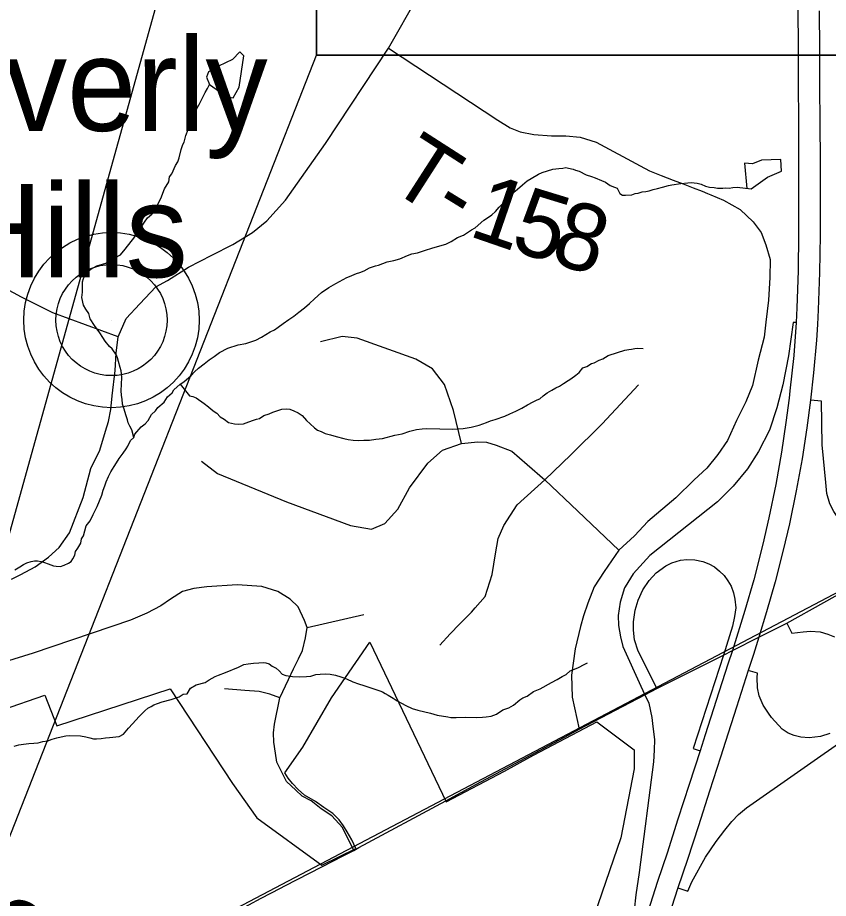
# Model space of a CAD drawing. Extents: x 44.2 to 78.2, y 4.5 to 26.5.
# Drawn here: x 50.361 to 51.048, y 22.487 to 23.234 of the extents above; entities that cross this region are included whole.
import ezdxf

# ---------------------------------------------------------------- set-up
doc = ezdxf.new("R2010")
doc.units = 0
for name, color, linetype in [('GM_X_Corporation', 7, 'Continuous'), ('GM_X_County_Road', 7, 'Continuous'), ('GM_X_Interchange_Ramps', 7, 'Continuous'), ('GM_X_Interstate_Route', 7, 'Continuous'), ('GM_X_Minor_Lake', 7, 'Continuous'), ('GM_X_Minor_River', 7, 'Continuous'), ('GM_X_Rail_Line', 7, 'Continuous'), ('GM_X_State_Route', 7, 'Continuous'), ('GM_X_Township_Road', 7, 'Continuous'), ('GM_X_Township_Road_Text', 7, 'Continuous'), ('GM_X_Unincorporated', 7, 'Continuous'), ('GM_X_Unincorporated_Location', 7, 'Continuous'), ('GM_X_Unincorporated_Text', 7, 'Continuous'), ('SH_Data', 7, 'Continuous')]:
    doc.layers.add(name, color=color, linetype=linetype)

msp = doc.modelspace()

# ---------------------------------------------------------------- linework, layer by layer
at = {"layer": 'GM_X_Corporation'}
msp.add_lwpolyline([(50.31156, 22.63401), (50.38364, 22.65883), (50.39385, 22.63306), (50.49002, 22.66436), (50.54291, 22.58409), (50.56344, 22.55477), (50.61853, 22.51475), (50.64753, 22.52885), (50.64407, 22.53609), (50.64003, 22.54311), (50.6369, 22.54819), (50.63346, 22.55312), (50.62793, 22.55864), (50.62046, 22.56357), (50.61315, 22.56865), (50.60403, 22.57403), (50.59851, 22.57881), (50.59387, 22.58404), (50.59014, 22.58852), (50.58715, 22.593), (50.60239, 22.61481), (50.62675, 22.65684), (50.65945, 22.70384), (50.72413, 22.56852), (50.77347, 22.59448), (50.79516, 22.60637), (50.79886, 22.60841), (50.8519, 22.63647), (50.88361, 22.61259), (50.88361, 22.59645), (50.87224, 22.5379), (50.84648, 22.46307)], dxfattribs=at)
at = {"layer": 'GM_X_County_Road'}
for points in [[(50.67528, 23.20811), (50.70031, 23.25252), (50.70921, 23.26368), (50.72749, 23.2982), (50.73832, 23.32832), (50.74576, 23.34795), (50.75659, 23.37604), (50.77337, 23.43186), (50.8174, 23.53966), (50.84536, 23.61043), (50.86798, 23.67979), (50.87273, 23.69294), (50.87551, 23.70196), (50.87354, 23.71004), (50.86808, 23.71791), (50.86065, 23.72293), (50.8576, 23.7273), (50.85497, 23.73517), (50.85476, 23.74587), (50.85912, 23.77099), (50.86196, 23.78672)], [(50.35523, 22.75754), (50.36339, 22.7613), (50.37531, 22.76789), (50.38661, 22.77605), (50.39571, 22.78421), (50.40449, 22.79676), (50.4161, 22.82657), (50.42262, 22.85131), (50.43022, 22.86673), (50.43524, 22.88304), (50.43775, 22.8912), (50.43964, 22.90124), (50.44089, 22.91285), (50.4434, 22.9345), (50.44403, 22.94925), (50.44591, 22.96306), (50.4525, 22.97874), (50.46429, 22.99111), (50.47791, 23.00539), (50.48764, 23.01075), (50.50553, 23.02204), (50.52529, 23.0324), (50.54318, 23.0415), (50.55981, 23.05154), (50.57205, 23.06158), (50.58773, 23.07915), (50.62162, 23.12716), (50.67528, 23.20811)]]:
    msp.add_lwpolyline(points, dxfattribs=at)
at = {"layer": 'GM_X_Interchange_Ramps'}
for points in [[(51.02104, 22.97511), (51.01857, 22.97527), (51.01465, 22.94684), (51.00975, 22.92233), (51.00452, 22.90272), (50.99831, 22.88377), (50.98916, 22.86579), (50.97969, 22.85109), (50.9676, 22.83638), (50.9542, 22.82298), (50.89701, 22.77756), (50.88288, 22.76188), (50.87595, 22.75088)], [(51.12221, 22.78472), (51.11418, 22.79428), (51.10871, 22.79237), (51.10379, 22.79125), (51.09767, 22.79057), (51.09122, 22.79069), (51.0851, 22.79159), (51.07777, 22.79375), (51.07059, 22.79718), (51.0643, 22.80152), (51.05786, 22.8078), (51.05289, 22.81477), (51.04962, 22.82141), (51.04704, 22.83), (51.04606, 22.8394), (51.04319, 22.87135), (51.04263, 22.90847), (51.03314, 22.90939)], [(50.90282, 22.6647), (50.8992, 22.67224), (50.88693, 22.69639), (50.88399, 22.706), (50.88292, 22.71401), (50.88292, 22.72108), (50.88439, 22.73122), (50.88693, 22.73949), (50.89093, 22.74843), (50.89627, 22.75617), (50.9024, 22.76284), (50.91041, 22.76884), (50.91561, 22.77138), (50.92295, 22.77351), (50.92842, 22.77418), (50.93509, 22.77378), (50.94176, 22.77245), (50.94697, 22.77031), (50.95164, 22.76791), (50.95604, 22.76431), (50.95991, 22.76057), (50.96311, 22.75604), (50.96592, 22.75137), (50.96792, 22.74576), (50.96912, 22.74056), (50.96978, 22.73295), (50.96872, 22.72562), (50.96698, 22.71748), (50.95933, 22.69286), (50.93376, 22.61367), (50.9395, 22.61186)], [(50.87595, 22.75088), (50.87542, 22.75004), (50.87169, 22.73798), (50.87016, 22.72657), (50.87038, 22.71802), (50.87191, 22.70837), (50.87411, 22.70025), (50.88912, 22.66664), (50.89262, 22.65931)], [(51.0131, 22.72011), (51.01724, 22.71163), (51.02699, 22.71267), (51.03333, 22.71326), (51.0413, 22.71267), (51.0478, 22.71075), (51.05355, 22.70854)], [(51.0496, 22.62647), (51.04168, 22.62382), (51.03213, 22.62277), (51.02492, 22.62342), (51.01936, 22.62481), (51.01426, 22.62682), (51.0092, 22.63018), (51.00015, 22.64009), (50.99758, 22.64358), (50.99299, 22.65036), (50.98962, 22.65833), (50.9881, 22.66526), (50.98784, 22.67404), (50.98826, 22.67755), (50.98029, 22.67996)], [(50.89262, 22.65931), (50.89602, 22.65216), (50.89857, 22.64), (50.89938, 22.63243), (50.90075, 22.62129), (50.90064, 22.6123), (50.89988, 22.60243), (50.88781, 22.50834), (50.88507, 22.48959), (50.88346, 22.47638), (50.87865, 22.45129), (50.85224, 22.3603), (50.85784, 22.35887)], [(50.92077, 22.49533), (50.9292, 22.49272), (50.93261, 22.50056), (50.94399, 22.52157), (50.95314, 22.5348), (50.96041, 22.54433), (50.96638, 22.55182), (50.97219, 22.55769), (50.97891, 22.56323), (51.06835, 22.62599), (51.07701, 22.63433), (51.08499, 22.64322), (51.08921, 22.64897), (51.09083, 22.65184)]]:
    msp.add_lwpolyline(points, dxfattribs=at)
at = {"layer": 'GM_X_Interstate_Route'}
for points in [[(51.02245, 23.24126), (51.02259, 23.20888), (51.02273, 23.1777), (51.02291, 23.1461), (51.02291, 23.11441), (51.02296, 23.08351), (51.02291, 23.05053), (51.02259, 23.01916), (51.02149, 22.98761), (51.02104, 22.97511), (51.01892, 22.94725), (51.01575, 22.9173), (51.01497, 22.91101), (51.0123, 22.89044), (51.00845, 22.86509), (51.00372, 22.83762), (50.99798, 22.80952), (50.99279, 22.78724), (50.98498, 22.75684), (50.97754, 22.73085), (50.96707, 22.69682), (50.96293, 22.6852), (50.95315, 22.65434), (50.94374, 22.62518), (50.9395, 22.61186), (50.93024, 22.58302), (50.92078, 22.55367), (50.9115, 22.52501), (50.90351, 22.50081), (50.89515, 22.47509)], [(51.04062, 23.23964), (51.04076, 23.20726), (51.0409, 23.17608), (51.04108, 23.14448), (51.04137, 23.11247), (51.04147, 23.08195), (51.04132, 23.04925), (51.04076, 23.01755), (51.03966, 22.98599), (51.03921, 22.97349), (51.03829, 22.96014), (51.03585, 22.93245), (51.03314, 22.90939), (51.03014, 22.88573), (51.02606, 22.85964), (51.02107, 22.83238), (51.01533, 22.80428), (51.01014, 22.782), (51.0031, 22.75502), (50.99594, 22.72977), (50.9894, 22.70822), (50.98481, 22.69344), (50.98029, 22.67996), (50.97042, 22.64885), (50.961, 22.61969), (50.95677, 22.60638), (50.9475, 22.57753), (50.93804, 22.54819), (50.92876, 22.51953), (50.92077, 22.49533), (50.9128, 22.47081)]]:
    msp.add_lwpolyline(points, dxfattribs=at)
at = {"layer": 'GM_X_Minor_Lake'}
for points in [[(50.52321, 23.1771), (50.53839, 23.16684), (50.54331, 23.16598), (50.54843, 23.17499), (50.55239, 23.2015), (50.54905, 23.20499), (50.54283, 23.19828), (50.53094, 23.19283), (50.52248, 23.18806)], [(50.97109, 23.08991), (50.98283, 23.08852), (50.99671, 23.09849), (51.00859, 23.10356), (51.00804, 23.11345), (50.99169, 23.11303)]]:
    msp.add_lwpolyline(points, dxfattribs=at)
at = {"layer": 'GM_X_Minor_River'}
for points in [[(50.52248, 23.18806), (50.52075, 23.18334), (50.52321, 23.1771)], [(50.45907, 22.87769), (50.45733, 22.88418), (50.45589, 22.88725), (50.45444, 22.88995), (50.45375, 22.89262), (50.45234, 22.89683), (50.45094, 22.90179), (50.44953, 22.906), (50.44925, 22.91018), (50.44857, 22.91323), (50.4483, 22.91741), (50.44881, 22.9227), (50.44896, 22.92877), (50.44834, 22.93409), (50.44765, 22.93714), (50.44626, 22.94211), (50.4452, 22.94517), (50.4445, 22.94746), (50.44083, 22.95287), (50.4386, 22.95482), (50.43492, 22.95947), (50.43272, 22.96256), (50.43016, 22.96642), (50.42576, 22.9726), (50.42211, 22.97839), (50.42108, 22.98296), (50.41851, 22.98644), (50.41632, 22.98992), (50.41496, 22.9964), (50.41546, 23.00093), (50.41568, 23.00965), (50.41651, 23.01266), (50.41892, 23.01753), (50.42279, 23.02046), (50.4278, 23.02336), (50.43545, 23.02544), (50.44045, 23.02796), (50.44509, 23.03125), (50.44778, 23.0327), (50.4517, 23.03753), (50.45994, 23.04793), (50.4612, 23.05282), (50.46508, 23.05576), (50.4706, 23.06395), (50.47448, 23.06726), (50.47684, 23.07024), (50.47924, 23.0751), (50.48203, 23.08034), (50.48527, 23.0886), (50.48885, 23.09457), (50.48933, 23.09873), (50.49129, 23.10133), (50.49451, 23.10845), (50.49649, 23.11144), (50.49771, 23.11482), (50.49941, 23.12198), (50.50066, 23.12612), (50.50185, 23.12836), (50.50313, 23.13401), (50.50516, 23.13889), (50.50597, 23.14114), (50.50838, 23.14639), (50.50922, 23.1494), (50.51284, 23.15727), (50.51441, 23.1595), (50.51682, 23.16475), (50.51802, 23.167), (50.51962, 23.17036), (50.52161, 23.17373), (50.52321, 23.1771)], [(50.99169, 23.11303), (50.98402, 23.10977), (50.9772, 23.11029), (50.97916, 23.08896)], [(50.44447, 22.85608), (50.44684, 22.85981), (50.45, 22.86428), (50.45275, 22.868), (50.45394, 22.87024), (50.45635, 22.87511), (50.45907, 22.87769), (50.45989, 22.88032), (50.46537, 22.88663), (50.46885, 22.88919), (50.47121, 22.89216), (50.47399, 22.89702), (50.47749, 22.90034), (50.47946, 22.90294), (50.48489, 22.90773), (50.48767, 22.91221), (50.49155, 22.91552), (50.49313, 22.91813), (50.49857, 22.92292), (50.50165, 22.92473), (50.50787, 22.93026), (50.5106, 22.93322), (50.51411, 22.93654), (50.51876, 22.94021), (50.52302, 22.94351), (50.52727, 22.94644), (50.53191, 22.94973), (50.53884, 22.95334), (50.54765, 22.95614), (50.55413, 22.95749), (50.56256, 22.9603), (50.56756, 22.96282), (50.57489, 22.96718), (50.57835, 22.96899), (50.58145, 22.97118), (50.58571, 22.97448), (50.59073, 22.97776), (50.59498, 22.98069), (50.59924, 22.98399), (50.60389, 22.98766), (50.60816, 22.99134), (50.61244, 22.9954), (50.61827, 23.00055), (50.62446, 23.00494), (50.63062, 23.00819), (50.63986, 23.01326), (50.64217, 23.01434), (50.64793, 23.01684), (50.65098, 23.01752), (50.65444, 23.01895), (50.65906, 23.02148), (50.66404, 23.02325), (50.66672, 23.02393), (50.674, 23.02678), (50.67973, 23.02776), (50.6847, 23.02915), (50.69123, 23.03201), (50.69506, 23.03343), (50.69965, 23.03445), (50.70653, 23.03654), (50.7119, 23.0383), (50.71687, 23.03968), (50.72376, 23.04178), (50.72837, 23.04393), (50.73377, 23.0472), (50.73876, 23.04935), (50.74571, 23.05372), (50.74879, 23.05553), (50.75618, 23.06216), (50.75926, 23.06398), (50.76274, 23.06654), (50.76586, 23.0695), (50.76899, 23.0732), (50.77249, 23.07653), (50.776, 23.08023), (50.7799, 23.08429), (50.78456, 23.08834), (50.78883, 23.09202), (50.79272, 23.09533), (50.79619, 23.09752), (50.80236, 23.10115), (50.80543, 23.10259), (50.81462, 23.10538), (50.81957, 23.10601), (50.823, 23.1063), (50.82566, 23.10661), (50.82793, 23.10617), (50.83171, 23.10531), (50.83397, 23.10449), (50.83698, 23.10366), (50.84298, 23.10046), (50.84751, 23.09921), (50.85051, 23.09799), (50.85577, 23.09558), (50.85916, 23.09435), (50.86327, 23.09159), (50.86702, 23.08998), (50.86928, 23.08916), (50.87036, 23.08685), (50.87144, 23.08455), (50.87369, 23.08335)], [(50.87369, 23.08335), (50.87635, 23.08329), (50.88167, 23.08353), (50.88436, 23.08459), (50.88703, 23.0849), (50.89047, 23.08595), (50.89352, 23.08625), (50.89619, 23.08694), (50.89964, 23.08798), (50.90346, 23.08902), (50.90767, 23.09005), (50.91264, 23.09144), (50.91569, 23.09211), (50.92331, 23.09305), (50.92902, 23.09366), (50.93207, 23.09396), (50.937, 23.09345), (50.94039, 23.09261), (50.94415, 23.09099), (50.94755, 23.09014), (50.95134, 23.08967), (50.95436, 23.08921), (50.95892, 23.08909), (50.9612, 23.08941), (50.96424, 23.08933), (50.96729, 23.08963), (50.97109, 23.08991)], [(50.49857, 22.92292), (50.50629, 22.91286), (50.50932, 22.9124), (50.51195, 22.91119), (50.51867, 22.90647), (50.52239, 22.90371), (50.52462, 22.90176), (50.52723, 22.8998), (50.52947, 22.89822), (50.53243, 22.89511), (50.5358, 22.89313), (50.53953, 22.89037), (50.54444, 22.88911), (50.54823, 22.88901), (50.55204, 22.88929), (50.55433, 22.88999), (50.5597, 22.89212), (50.56315, 22.89317), (50.56582, 22.89386), (50.56931, 22.89642), (50.5739, 22.89782), (50.57698, 22.89925), (50.58119, 22.90066), (50.58463, 22.90171), (50.58882, 22.90198), (50.59147, 22.90153), (50.59485, 22.9003), (50.59861, 22.89868), (50.60197, 22.89632), (50.60566, 22.89206), (50.60863, 22.88932), (50.61234, 22.88581), (50.61495, 22.88385), (50.61796, 22.88263), (50.62134, 22.88103), (50.62586, 22.87977), (50.63077, 22.8785), (50.63718, 22.87682), (50.64096, 22.87596), (50.64512, 22.87548), (50.64967, 22.87498), (50.65423, 22.87524), (50.65918, 22.87549), (50.66451, 22.8761), (50.67022, 22.87671), (50.68055, 22.87948), (50.68666, 22.88084), (50.69317, 22.88294), (50.6989, 22.88431), (50.70385, 22.88494), (50.70766, 22.88521), (50.72967, 22.88464), (50.73462, 22.88489), (50.73842, 22.88517), (50.74529, 22.8865), (50.74873, 22.88717), (50.75217, 22.88822), (50.7583, 22.89033), (50.76176, 22.89176), (50.76558, 22.8928), (50.77401, 22.89561), (50.77824, 22.89778), (50.78323, 22.89992), (50.78823, 22.90244), (50.79324, 22.90535), (50.79787, 22.90788), (50.80133, 22.90969), (50.80363, 22.91038), (50.80635, 22.91297), (50.80983, 22.91553), (50.81369, 22.9177), (50.81716, 22.91989), (50.82023, 22.92132), (50.82371, 22.92351), (50.82757, 22.92606), (50.82988, 22.92752), (50.83414, 22.93044), (50.83685, 22.93264), (50.83999, 22.93673), (50.84344, 22.93778), (50.8473, 22.94033), (50.8496, 22.94103), (50.85383, 22.94319), (50.85689, 22.94425), (50.86153, 22.94717), (50.86956, 22.94961), (50.87569, 22.95172), (50.87913, 22.95239), (50.88142, 22.95271), (50.88408, 22.95302), (50.88637, 22.95334), (50.8913, 22.95321)], [(50.35825, 22.76543), (50.36249, 22.76798), (50.36557, 22.76979), (50.36827, 22.77124), (50.37209, 22.77228), (50.37477, 22.77296), (50.37743, 22.77289), (50.38045, 22.77243), (50.38347, 22.7716), (50.38648, 22.77038), (50.39099, 22.76875), (50.39326, 22.76831), (50.39706, 22.76821), (50.40013, 22.76927), (50.40359, 22.77107), (50.4059, 22.77253), (50.40748, 22.77476), (50.40907, 22.77775), (50.40953, 22.78078), (50.4115, 22.78376), (50.41427, 22.78786), (50.41474, 22.79164), (50.41633, 22.79425), (50.41881, 22.80253), (50.42196, 22.80699), (50.42475, 22.81223), (50.42796, 22.81897), (50.43201, 22.82873), (50.43325, 22.83286), (50.43449, 22.83662), (50.43571, 22.84), (50.43772, 22.8445), (50.43973, 22.84862), (50.4425, 22.8531), (50.44447, 22.85608)], [(50.4249, 22.62187), (50.42755, 22.6218), (50.43136, 22.62208), (50.43517, 22.62274), (50.4386, 22.62303), (50.4466, 22.62396), (50.45044, 22.62575), (50.45475, 22.63095), (50.45788, 22.63466), (50.46374, 22.64095), (50.46608, 22.64354), (50.46842, 22.64576), (50.47113, 22.64796), (50.47383, 22.64941), (50.47614, 22.65086), (50.47921, 22.65192), (50.48304, 22.65334), (50.49069, 22.65541), (50.49758, 22.65751), (50.50105, 22.65969), (50.50448, 22.65998), (50.50726, 22.66484), (50.51189, 22.66775), (50.51954, 22.66983), (50.52301, 22.67201), (50.52802, 22.67491), (50.53109, 22.67597), (50.53684, 22.6781), (50.54797, 22.68273), (50.55259, 22.68489), (50.55602, 22.68556), (50.56059, 22.6862), (50.56516, 22.68646), (50.56896, 22.68674), (50.57123, 22.6863), (50.57387, 22.68547), (50.57648, 22.6835), (50.57986, 22.6819), (50.58245, 22.67956), (50.58505, 22.67684), (50.58805, 22.67562), (50.59373, 22.67471), (50.59942, 22.67456), (50.6055, 22.67478), (50.60931, 22.67506), (50.61352, 22.67647), (50.61733, 22.67675), (50.62151, 22.67702), (50.62569, 22.67691), (50.63022, 22.67603), (50.63474, 22.6744), (50.63964, 22.67275), (50.64489, 22.67034), (50.64979, 22.6687), (50.65431, 22.66706), (50.66184, 22.66459), (50.66523, 22.66336), (50.66787, 22.66253), (50.67012, 22.66172), (50.67237, 22.66052), (50.67499, 22.65893), (50.67911, 22.65655), (50.68247, 22.65419), (50.68996, 22.6502), (50.69522, 22.64779), (50.70012, 22.64614), (50.71069, 22.64359), (50.71634, 22.64193), (50.72542, 22.64055), (50.72807, 22.6401), (50.73263, 22.63999), (50.74061, 22.64016), (50.7501, 22.63991), (50.75504, 22.64016), (50.75809, 22.64046), (50.76228, 22.6411), (50.76688, 22.64288), (50.77229, 22.64653), (50.77727, 22.6483), (50.78113, 22.65047), (50.78656, 22.65488), (50.78926, 22.6567), (50.79271, 22.65813), (50.79813, 22.66216), (50.80388, 22.66428), (50.81352, 22.66972), (50.81814, 22.67225), (50.82238, 22.6748), (50.82585, 22.6766), (50.82934, 22.67954), (50.83586, 22.68203), (50.84164, 22.68529), (50.84394, 22.68637)], [(50.35751, 22.61567), (50.36172, 22.6167), (50.36553, 22.61735), (50.3701, 22.61799), (50.37429, 22.61826), (50.3781, 22.61854), (50.38192, 22.61958), (50.38611, 22.62023), (50.38995, 22.62164), (50.39377, 22.62268), (50.3976, 22.62372), (50.40141, 22.62438), (50.40484, 22.62467), (50.41395, 22.62443), (50.41848, 22.62355), (50.42188, 22.62271), (50.4249, 22.62187)]]:
    msp.add_lwpolyline(points, dxfattribs=at)
at = {"layer": 'GM_X_Rail_Line'}
msp.add_lwpolyline([(53.13586, 22.93662), (51.70946, 23.06925), (51.30353, 22.9372), (51.24061, 22.89778), (51.15864, 22.80886), (51.10211, 22.77052), (50.54595, 22.47795)], dxfattribs=at)
at = {"layer": 'GM_X_State_Route'}
for p, q in [((50.74993, 22.58335), (50.82814, 22.62543)), ((50.72386, 22.56932), (50.74993, 22.58335)), ((50.64999, 22.52958), (50.72386, 22.56932))]:
    msp.add_line(p, q, dxfattribs=at)
for points in [[(50.94914, 22.68778), (50.95933, 22.69286), (50.96707, 22.69682), (50.9894, 22.70822), (51.0131, 22.72011), (51.07593, 22.75516), (51.09748, 22.7682), (51.12221, 22.78472)], [(50.82814, 22.62543), (50.83683, 22.63011), (50.89262, 22.65931), (50.90282, 22.6647), (50.94914, 22.68778)], [(50.63665, 22.52261), (50.64565, 22.52724), (50.64999, 22.52958)], [(50.58364, 22.49526), (50.58712, 22.49709), (50.61865, 22.51336), (50.63665, 22.52261)], [(50.53109, 22.46695), (50.54635, 22.47535), (50.56712, 22.48659), (50.58364, 22.49526)]]:
    msp.add_lwpolyline(points, dxfattribs=at)
at = {"layer": 'GM_X_Township_Road'}
msp.add_line((50.60611, 22.71637), (50.65417, 22.72735), dxfattribs=at)
for points in [[(50.67528, 23.20811), (50.76793, 23.14699), (50.77834, 23.14039), (50.78689, 23.13692), (50.79843, 23.13485), (50.81358, 23.13359), (50.82555, 23.13352), (50.83771, 23.13251), (50.85139, 23.1282), (50.88876, 23.10819), (50.89648, 23.10401), (50.90655, 23.09996), (50.91675, 23.09609), (50.9253, 23.09286), (50.93379, 23.08944), (50.94115, 23.08672), (50.9459, 23.08478)], [(50.44591, 22.96306), (50.39037, 22.98345), (50.36398, 22.99663), (50.34334, 23.0078), (50.32287, 23.02008), (50.30126, 23.03114), (50.2611, 23.05687), (50.24112, 23.07278), (50.22724, 23.08192), (50.21709, 23.08767), (50.19176, 23.10331), (50.17444, 23.11238)], [(50.9459, 23.08478), (50.94875, 23.08361), (50.95946, 23.07889), (50.97351, 23.07118), (50.98468, 23.06069), (50.99136, 23.05171), (50.99517, 23.04123), (50.99908, 23.02862), (50.99875, 23.01344), (50.99757, 22.99409), (50.99528, 22.97552), (50.99387, 22.96264), (50.9889, 22.94337), (50.9839, 22.92183), (50.97829, 22.90789), (50.97037, 22.8921), (50.96281, 22.87517), (50.9546, 22.86319), (50.94526, 22.85161), (50.93443, 22.84158), (50.91895, 22.82633), (50.8952, 22.80632), (50.88377, 22.7943), (50.87058, 22.78199), (50.85827, 22.76381), (50.84969, 22.75078), (50.84429, 22.73711), (50.84048, 22.72622), (50.83818, 22.71719), (50.83341, 22.69827), (50.83042, 22.67603), (50.83111, 22.65722), (50.83683, 22.63011)], [(50.73707, 22.87259), (50.73041, 22.90057), (50.72268, 22.92269), (50.71256, 22.93575), (50.69836, 22.94403), (50.6486, 22.96186), (50.63583, 22.96319), (50.61747, 22.95866)], [(50.71886, 22.70137), (50.72741, 22.71107), (50.73554, 22.71926), (50.74135, 22.72521), (50.74561, 22.7293), (50.74872, 22.73303), (50.75713, 22.74271), (50.763, 22.76147), (50.76593, 22.77876), (50.76827, 22.79196), (50.77298, 22.80297), (50.7844, 22.82038), (50.80795, 22.84168), (50.82983, 22.86289), (50.85651, 22.88928), (50.88729, 22.92233)], [(50.51642, 22.85767), (50.53002, 22.84701), (50.58864, 22.82303), (50.643, 22.80304), (50.66086, 22.79984), (50.67205, 22.80464), (50.68297, 22.8169), (50.6931, 22.83502), (50.70855, 22.8558), (50.72108, 22.86699), (50.73707, 22.87259), (50.75092, 22.87392), (50.75839, 22.87365), (50.76665, 22.87099), (50.77992, 22.86603), (50.7928, 22.85484)], [(50.7928, 22.85484), (50.80795, 22.84168), (50.83567, 22.81503), (50.87058, 22.78199)], [(50.64565, 22.52724), (50.6361, 22.54673), (50.62706, 22.55659), (50.61803, 22.56254), (50.60961, 22.56932), (50.60201, 22.57322), (50.59646, 22.57835), (50.58866, 22.58575), (50.58045, 22.60197), (50.57921, 22.60978), (50.57798, 22.61902), (50.57777, 22.62703), (50.57837, 22.63424), (50.58291, 22.65681), (50.59041, 22.67231), (50.59461, 22.68145), (50.59883, 22.68987), (50.60232, 22.69675), (50.60478, 22.70764), (50.60611, 22.71637), (50.60406, 22.72232), (50.59852, 22.73393), (50.59184, 22.74049), (50.58127, 22.74697), (50.56781, 22.75128), (50.54687, 22.75272), (50.5211, 22.75103), (50.51004, 22.74951), (50.50046, 22.74681), (50.49037, 22.74032), (50.48207, 22.73485), (50.47016, 22.72869), (50.4564, 22.72252), (50.37378, 22.69462), (50.28247, 22.66628)], [(50.58291, 22.65681), (50.57439, 22.65969), (50.56535, 22.66194), (50.55334, 22.66287), (50.53619, 22.6643)]]:
    msp.add_lwpolyline(points, dxfattribs=at)
at = {"layer": 'GM_X_Unincorporated'}
for radius in [0.0744, 0.04716]:
    msp.add_circle((50.44021, 22.97726), radius, dxfattribs=at)
at = {"layer": 'GM_X_Unincorporated_Location'}
msp.add_line((50.44021, 22.97726), (50.44021, 22.97726), dxfattribs=at)
at = {"layer": 'SH_Data'}
msp.add_line((50.61408, 23.20201), (52.26449, 23.20201), dxfattribs=at)
for points in [[(50.61408, 23.7345), (50.10755, 21.91224), (50.61408, 23.20201)], [(50.61408, 23.7345), (52.26449, 23.7345), (52.26449, 23.20201), (50.61408, 23.20201)]]:
    msp.add_lwpolyline(points, close=True, dxfattribs=at)
msp.add_lwpolyline([(52.26449, 23.20201), (52.26449, 23.7345), (50.61408, 23.7345), (50.61408, 23.20201)], dxfattribs=at)

# ---------------------------------------------------------------- texts
at = {"layer": 'GM_X_Township_Road_Text'}
for s, height, rotation, p in [('T', 0.05682, 327.26684, (50.67293, 23.09082)), ('1', 0.05682, 340.98027, (50.74187, 23.04916)), ('5', 0.05682, 343.00707, (50.77704, 23.03708)), ('-', 0.05682, 328.43394, (50.70975, 23.06717)), ('8', 0.05682, 343.07299, (50.81058, 23.02683)), ('T-82', 0.056818, 339.38696, (50.2219, 22.47762))]:
    msp.add_text(s, height=height, rotation=rotation, dxfattribs=at).set_placement(p)
at = {"layer": 'GM_X_Unincorporated_Text'}
for s, p in [('Beverly', (50.22054, 23.13782)), ('Hills', (50.30554, 23.01365))]:
    msp.add_text(s, height=0.078977, rotation=0.00001, dxfattribs=at).set_placement(p)

doc.saveas('drawing.dxf')
